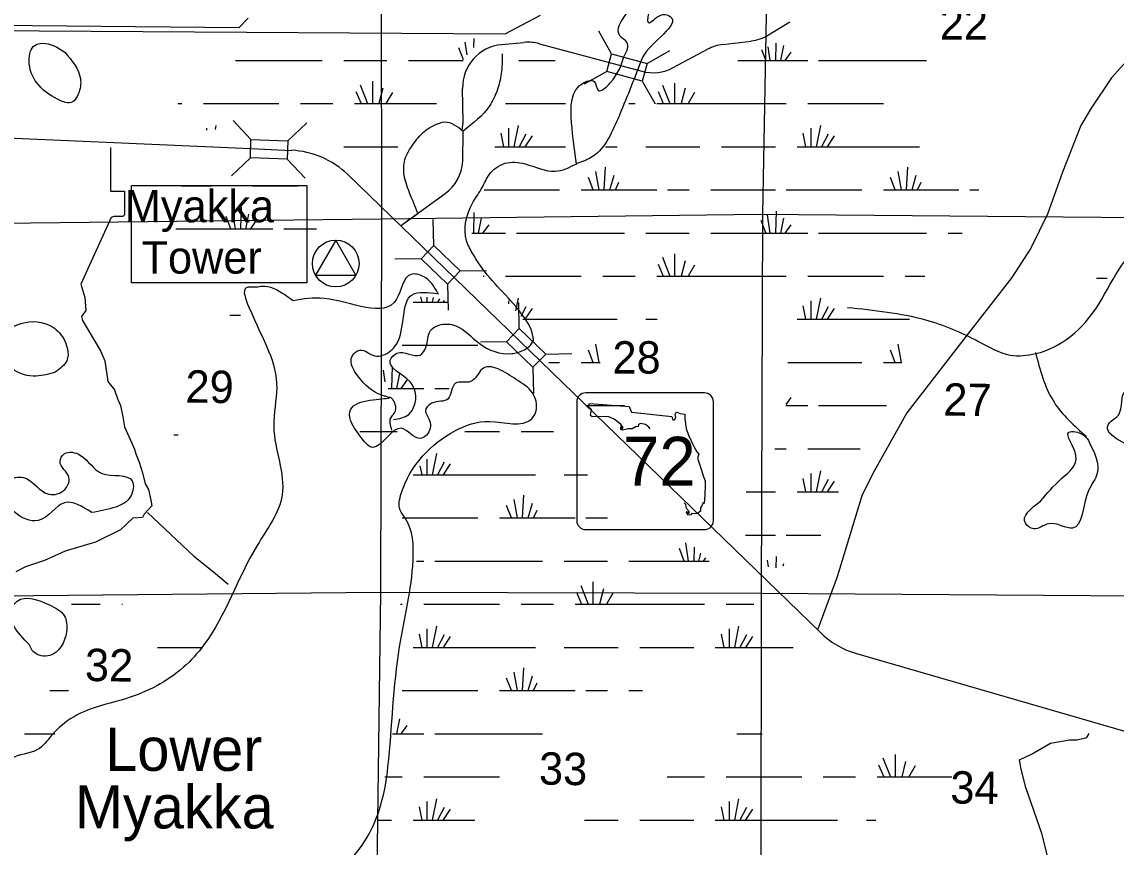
# Model space of a CAD drawing. Extents: x 408847 to 817539, y 923858 to 1151780.
# Drawn here: x 547942 to 563149, y 1047697 to 1059169 of the extents above; entities that cross this region are included whole.
import ezdxf

# ---------------------------------------------------------------- set-up
doc = ezdxf.new("R2010")
doc.units = 0
for name, color, linetype in [('Bridges', 7, 'Continuous'), ('Culture', 7, 'Continuous'), ('Lakes and Ponds', 7, 'Continuous'), ('Level 12', 7, 'Continuous'), ('Level 41', 7, 'Continuous'), ('Level 42', 7, 'Continuous'), ('Level 43', 7, 'Continuous'), ('Level 47', 7, 'Continuous'), ('Local Roads Paved', 7, 'Continuous'), ('Narrow River Creek and Branch and Slough', 7, 'Continuous'), ('Roadshields State Highways', 7, 'Continuous'), ('Section Lines', 7, 'Continuous'), ('State Park', 7, 'Continuous'), ('State Routes Highway Center Lines', 7, 'Continuous'), ('Swamps', 7, 'Continuous')]:
    doc.layers.add(name, color=color, linetype=linetype)

msp = doc.modelspace()

# ---------------------------------------------------------------- linework, layer by layer
at = {"layer": 'Bridges'}
for p, q in [((556137, 1058726), (555958, 1059041)), ((556631, 1058590), (556945, 1058769)), ((556069, 1058480), (555754, 1058301)), ((556562, 1058343), (556741, 1058028)), ((551125, 1057534), (550878, 1057798)), ((551637, 1057517), (551901, 1057765)), ((551117, 1057278), (550853, 1057030)), ((551629, 1057261), (551877, 1056997)), ((553667, 1056061), (553660, 1056423)), ((553489, 1055877), (553127, 1055871)), ((554035, 1055706), (554397, 1055712)), ((553857, 1055522), (553864, 1055160)), ((554854, 1054906), (554848, 1055268)), ((554676, 1054722), (554314, 1054716)), ((555223, 1054551), (555585, 1054557)), ((555045, 1054367), (555051, 1054005))]:
    msp.add_line(p, q, dxfattribs=at)
for points in [[(556137, 1058726), (556631, 1058590), (556562, 1058343), (556069, 1058480)], [(551125, 1057534), (551637, 1057517), (551629, 1057261), (551117, 1057278)], [(553667, 1056061), (554035, 1055706), (553857, 1055522), (553489, 1055877)], [(554854, 1054906), (555223, 1054551), (555045, 1054367), (554676, 1054722)]]:
    msp.add_lwpolyline(points, close=True, dxfattribs=at)
at = {"layer": 'Culture'}
msp.add_lwpolyline([(552023, 1055648), (552585, 1055648), (552304, 1056135)], close=True, dxfattribs=at)
msp.add_circle((552304, 1055810), 325, dxfattribs=at)
at = {"layer": 'Lakes and Ponds'}
for p, q in [((555641, 1057198), (555650, 1057193)), ((553732, 1055390), (553722, 1055400))]:
    msp.add_line(p, q, dxfattribs=at)
for points in [[(556309, 1058685), (556351, 1058886), (556255, 1058971), (556356, 1059297), (556451, 1059406), (556733, 1059847), (557074, 1059998), (557133, 1060207), (557234, 1060270), (557345, 1060172), (557257, 1059852), (557146, 1059776), (556787, 1059581), (556664, 1059155), (556850, 1059271), (556951, 1059245), (556570, 1058681), (556545, 1058620)], [(548540, 1058747), (548226, 1058872), (548121, 1058842), (548043, 1058632), (548437, 1058094), (548650, 1058059), (548726, 1058164), (548756, 1058378), (548540, 1058747)], [(555650, 1057193), (555582, 1057770), (555758, 1058328), (555896, 1058341), (555949, 1058220), (556116, 1058320), (556309, 1058685)], [(556545, 1058620), (556223, 1057818), (555846, 1057279), (555641, 1057198)], [(553722, 1055400), (553521, 1055631), (553348, 1055658), (553150, 1055314), (552146, 1055324), (551711, 1055293)], [(551711, 1055293), (551590, 1055377), (551281, 1055491), (551201, 1055481), (551060, 1055471), (551097, 1055204), (551483, 1054080), (551442, 1053545), (551559, 1052590), (551211, 1051890), (550468, 1050503), (550189, 1050197), (549395, 1049764), (548804, 1049579), (548462, 1049360), (548350, 1049243), (548161, 1049052), (547794, 1048927), (547627, 1048491), (547638, 1047921), (547608, 1047674), (546454, 1047613), (546109, 1047460), (545990, 1047112), (546360, 1046135), (546342, 1045807), (546223, 1045704), (545885, 1045633), (545598, 1044356), (545089, 1043682), (544808, 1042649), (544826, 1042544), (544941, 1042105), (544737, 1042014), (544903, 1041875), (545016, 1041929), (545126, 1042134), (545113, 1042460), (545172, 1043016), (545967, 1044163), (546271, 1044606), (546310, 1044928), (546115, 1045140), (546091, 1045363), (546521, 1045487), (546653, 1045452), (547247, 1045445), (547839, 1045684), (548058, 1045859), (548124, 1046099), (548220, 1046456), (548064, 1046678), (547763, 1046895), (547895, 1046973), (548594, 1046679), (549802, 1046381), (550350, 1046366), (551126, 1046460), (552019, 1047061), (552705, 1047775), (553018, 1048713), (553030, 1048817), (553191, 1050483), (553379, 1051686), (553269, 1052268), (553198, 1052383), (553214, 1052614), (553967, 1053487), (554441, 1053615), (555027, 1053653), (555088, 1053763), (555037, 1054014), (554817, 1054195), (554337, 1054341), (554178, 1054169), (553968, 1054145), (553866, 1053930), (553637, 1053867), (553551, 1053758), (553598, 1053653), (553584, 1053445), (553479, 1053378), (553217, 1053519), (552820, 1053254), (552629, 1053430), (552500, 1053747), (552582, 1053852), (553029, 1053954), (552980, 1053968), (552656, 1054190), (552535, 1054529), (552638, 1054606), (552849, 1054526), (552956, 1054536), (553148, 1054690), (553366, 1055376), (553732, 1055390)], [(548407, 1054299), (548565, 1054459), (548505, 1054791), (548312, 1054958), (547877, 1054957), (547686, 1054786), (547688, 1054665), (547819, 1054346), (548142, 1054245), (548407, 1054299)], [(563956, 1053465), (563984, 1053534), (563904, 1053662), (563554, 1053810), (563404, 1054017), (563292, 1054037), (563182, 1053703), (563079, 1053619), (563027, 1053513), (563113, 1053403), (563451, 1053266), (563956, 1053465)], [(562102, 1052511), (561889, 1052199), (562004, 1052123), (562211, 1052192), (562542, 1052129), (562767, 1052653), (562887, 1052895), (562778, 1053319), (562700, 1053424), (562492, 1053464), (562591, 1053139), (562389, 1052819), (562102, 1052511)], [(548913, 1052348), (549249, 1052425), (549453, 1052570), (549475, 1052787), (549054, 1052892), (548754, 1053145), (548532, 1053163), (548472, 1053058), (548597, 1052839), (548490, 1052630), (548263, 1052624), (547963, 1052837), (547755, 1052780), (547696, 1052675), (548169, 1052236), (548535, 1052485), (548913, 1052348)], [(548042, 1050514), (548107, 1050409), (548332, 1050361), (548562, 1050689), (548529, 1050918), (548324, 1051064), (547878, 1051117), (547795, 1051010), (548042, 1050514)]]:
    msp.add_spline(points, degree=3, dxfattribs=at)
at = {"layer": 'Level 12'}
for p, q in [((545296, 1059144), (550961, 1059091)), ((550961, 1059091), (551089, 1059219))]:
    msp.add_line(p, q, dxfattribs=at)
at = {"layer": 'Level 41'}
msp.add_lwpolyline([(549466, 1056894), (551901, 1056894), (551901, 1055540), (549466, 1055540)], close=True, dxfattribs=at)
at = {"layer": 'Local Roads Paved'}
for p, q in [((558317, 1058987), (558614, 1059169)), ((558317, 1058987), (558614, 1059169)), ((554608, 1058853), (554920, 1058883)), ((554608, 1058853), (554920, 1058883)), ((555134, 1058865), (556556, 1058483)), ((555134, 1058865), (556556, 1058483)), ((557682, 1058855), (558077, 1058903)), ((557682, 1058855), (558077, 1058903)), ((556994, 1058533), (557472, 1058788)), ((556994, 1058533), (557472, 1058788)), ((554075, 1057775), (554066, 1058244)), ((554075, 1057775), (554066, 1058244)), ((554060, 1057659), (554075, 1057775)), ((554070, 1057231), (554074, 1057652)), ((553205, 1056332), (553824, 1056782)), ((553205, 1056332), (553446, 1056507))]:
    msp.add_line(p, q, dxfattribs=at)
for points in [[(563504, 1058861), (563086, 1058389), (562801, 1057971), (562658, 1057729), (562405, 1057080), (562196, 1056497), (561965, 1056024), (561701, 1055617), (560998, 1054715), (560239, 1053736), (559767, 1052889), (559613, 1052581), (559272, 1051455), (559004, 1050727)], [(549173, 1057425), (549173, 1056817), (549368, 1056817), (549368, 1056817), (549368, 1056623), (549368, 1056485), (549345, 1056462), (549219, 1056462), (549185, 1056451), (548761, 1055522), (548818, 1055339), (548829, 1055156), (548772, 1055075), (548784, 1055018), (549036, 1054594), (549093, 1054457), (549139, 1054170), (549230, 1054056), (549276, 1053918), (549311, 1053838), (549345, 1053677), (549368, 1053540), (549471, 1053311), (549505, 1053230), (549528, 1053162), (549574, 1053047), (549620, 1052898), (549654, 1052749), (549700, 1052669), (549734, 1052520), (549746, 1052440), (549643, 1052325), (549620, 1052279), (549482, 1052268), (549311, 1052107), (548967, 1051935), (548543, 1051809), (548257, 1051683), (547993, 1051592), (547856, 1051523)], [(549689, 1052348), (550330, 1051741), (550605, 1051523), (550811, 1051351)], [(562444, 1045932), (562433, 1046447), (562301, 1047151), (562115, 1047888), (561895, 1048526), (561829, 1048779), (561807, 1048911), (561972, 1048988), (562235, 1049142), (562499, 1049186), (562609, 1049186), (562741, 1049219), (562774, 1049274)]]:
    msp.add_lwpolyline(points, dxfattribs=at)
for centre, start, end in [((558004, 1059499), 277.0197, 301.4719), ((558004, 1059499), 277.0197, 301.4719), ((554666, 1058255), 95.5848, 181.0944), ((554666, 1058255), 95.5848, 181.0944), ((554978, 1058286), 74.9456, 95.5849), ((554978, 1058286), 74.9456, 95.5849), ((557755, 1058259), 97.0196, 118.1097), ((557755, 1058259), 97.0196, 118.1097), ((556712, 1059062), 254.9456, 298.1098), ((556712, 1059062), 254.9456, 298.1098), ((553471, 1057267), 306.0117, 356.5362)]:
    msp.add_arc(centre, 600, start, end, dxfattribs=at)
for points in [[(554615, 1058724), (554604, 1058448), (554546, 1058217), (554444, 1058006), (554074, 1057652)], [(553446, 1056507), (553330, 1056793), (553255, 1057037), (553266, 1057253), (553382, 1057471), (553525, 1057637), (553669, 1057730), (553820, 1057778), (554074, 1057652)]]:
    msp.add_spline(points, degree=3, dxfattribs=at)
at = {"layer": 'Narrow River Creek and Branch and Slough'}
msp.add_lwpolyline([(554834, 1054573), (554927, 1054611), (554991, 1054654), (555011, 1054674), (555040, 1054718), (555052, 1054741)], dxfattribs=at)
for points in [[(555052, 1054741), (555043, 1054802), (554873, 1055131), (554319, 1055772), (554214, 1055938), (554123, 1056124), (554214, 1056666), (554339, 1056867), (554435, 1057043), (554656, 1057203), (554934, 1057195), (555355, 1057092), (555645, 1057193)], [(559417, 1055199), (560500, 1055027), (561234, 1054728), (561677, 1054538), (562030, 1054557), (562908, 1055247), (563657, 1056051), (564199, 1056046), (564363, 1056264), (564803, 1056101), (565241, 1056102), (565613, 1055580), (565587, 1055366), (565483, 1055119), (565670, 1054911), (566108, 1054655), (566363, 1054220)], [(553105, 1053643), (553318, 1053712), (553396, 1053833), (553336, 1054165), (553062, 1054464), (553154, 1054565), (553476, 1054538), (553558, 1054643), (553620, 1054877), (553737, 1054953), (553973, 1054943), (554295, 1054703), (554751, 1054557), (554834, 1054573)], [(562028, 1054575), (562281, 1053890), (562737, 1053405)], [(553046, 1053955), (553080, 1053936), (553109, 1053896), (553134, 1053801), (553123, 1053745), (553090, 1053697), (553057, 1053642), (553060, 1053576), (553069, 1053533), (553085, 1053495)]]:
    msp.add_spline(points, degree=3, dxfattribs=at)
at = {"layer": 'Roadshields State Highways'}
for p, q in [((557428, 1054011), (555778, 1054011)), ((555653, 1053886), (555653, 1052236)), ((557553, 1052236), (557553, 1053886)), ((555778, 1052111), (557428, 1052111))]:
    msp.add_line(p, q, dxfattribs=at)
for points in [[(556672, 1053512), (556653, 1053537), (556610, 1053574), (556541, 1053584), (556511, 1053570), (556508, 1053541), (556478, 1053544), (556425, 1053514), (556366, 1053514), (556290, 1053495), (556264, 1053501), (556267, 1053544), (556284, 1053514), (556300, 1053531), (556264, 1053574), (556208, 1053617), (556171, 1053646), (556099, 1053679), (556023, 1053683), (555868, 1053679), (555845, 1053696), (555858, 1053782), (555812, 1053824), (555829, 1053864)], [(555829, 1053864), (556382, 1053824), (556412, 1053745), (556976, 1053683), (556989, 1053636), (557012, 1053636), (557029, 1053669), (557019, 1053709), (557038, 1053749), (557088, 1053725), (557154, 1053716), (557154, 1053653), (557174, 1053518), (557207, 1053422), (557276, 1053274), (557322, 1053194), (557348, 1053158), (557329, 1053102), (557355, 1053033), (557388, 1052937), (557411, 1052858), (557437, 1052789), (557437, 1052726), (557431, 1052601), (557427, 1052528), (557424, 1052472), (557411, 1052489), (557394, 1052452), (557371, 1052413), (557371, 1052367), (557332, 1052337), (557289, 1052330), (557253, 1052337), (557240, 1052317), (557197, 1052310), (557177, 1052347), (557187, 1052363), (557200, 1052340), (557216, 1052334), (557216, 1052363), (557180, 1052406), (557167, 1052459), (557145, 1052483)]]:
    msp.add_lwpolyline(points, dxfattribs=at)
for centre, start, end in [((555778, 1053886), 90, 180), ((557428, 1053886), 0, 90), ((555778, 1052236), 180, 270), ((557428, 1052236), 270, 0)]:
    msp.add_arc(centre, 125, start, end, dxfattribs=at)
at = {"layer": 'Section Lines'}
for p, q in [((552930, 1061674), (552941, 1056432)), ((558334, 1061654), (558233, 1056494)), ((547660, 1056371), (552941, 1056432)), ((552941, 1056432), (552927, 1051241)), ((552941, 1056432), (558213, 1056494)), ((558213, 1056494), (563464, 1056450)), ((558233, 1056494), (558217, 1051227)), ((547615, 1051190), (552927, 1051241)), ((552927, 1051241), (552856, 1046025)), ((552927, 1051241), (558217, 1051227)), ((558218, 1051275), (558207, 1045966)), ((558217, 1051227), (563447, 1051191))]:
    msp.add_line(p, q, dxfattribs=at)
at = {"layer": 'State Park'}
msp.add_lwpolyline([(543571, 1043078), (543581, 1043265), (542259, 1043316), (542432, 1046159), (542425, 1059084), (554660, 1059003), (555149, 1059262)], dxfattribs=at)
at = {"layer": 'State Routes Highway Center Lines'}
for p, q in [((551123, 1057408), (551688, 1057383)), ((552471, 1057046), (559039, 1050679)), ((559540, 1050388), (569161, 1047598))]:
    msp.add_line(p, q, dxfattribs=at)
msp.add_lwpolyline([(539784, 1058895), (539798, 1058892), (539799, 1058892), (545306, 1057682), (545327, 1057677), (545347, 1057673), (545368, 1057670), (545389, 1057667), (545410, 1057664), (545430, 1057661), (545451, 1057659), (545472, 1057657), (545493, 1057656), (545511, 1057655), (551123, 1057408)], dxfattribs=at)
for centre, start, end in [((551635, 1056185), 45.8894, 87.4828), ((559874, 1051540), 225.8893, 253.8269)]:
    msp.add_arc(centre, 1200, start, end, dxfattribs=at)
at = {"layer": 'Swamps'}
for p, q in [((558488, 1058633), (558531, 1058839)), ((558550, 1058633), (558634, 1058747)), ((552415, 1058634), (553015, 1058634)), ((553315, 1058634), (553915, 1058634)), ((558115, 1058634), (558865, 1058634)), ((559015, 1058634), (560515, 1058634)), ((552644, 1058296), (552747, 1058034)), ((552813, 1058345), (552813, 1058034)), ((552958, 1058248), (552905, 1058033)), ((557158, 1058248), (557105, 1058033)), ((552584, 1058200), (552655, 1058034)), ((553091, 1058187), (553002, 1058034)), ((556784, 1058200), (556855, 1058034)), ((557291, 1058187), (557202, 1058034)), ((550465, 1058034), (551515, 1058034)), ((551815, 1058034), (552265, 1058034)), ((554665, 1058034), (555498, 1058034)), ((556375, 1058034), (556465, 1058034)), ((556765, 1058034), (558115, 1058034)), ((558115, 1058034), (558565, 1058034)), ((558865, 1058034), (559915, 1058034)), ((554597, 1057620), (554634, 1057434)), ((554706, 1057692), (554706, 1057434)), ((554839, 1057728), (554780, 1057434)), ((554947, 1057608), (554853, 1057433)), ((558797, 1057620), (558834, 1057434)), ((558906, 1057692), (558906, 1057434)), ((559039, 1057728), (558980, 1057434)), ((559147, 1057608), (559053, 1057433)), ((555032, 1057583), (554933, 1057434)), ((559232, 1057583), (559133, 1057434)), ((552415, 1057434), (553165, 1057434)), ((554515, 1057434), (555498, 1057434)), ((556054, 1057434), (556215, 1057434)), ((556615, 1057434), (557365, 1057434)), ((557665, 1057434), (558115, 1057434)), ((558115, 1057434), (558415, 1057434)), ((558715, 1057434), (560415, 1057434)), ((556036, 1056834), (556054, 1057150)), ((560236, 1056834), (560254, 1057150)), ((555880, 1056834), (555815, 1057006)), ((555965, 1056834), (555919, 1057088)), ((556113, 1056834), (556171, 1057038)), ((560080, 1056834), (560015, 1057006)), ((560165, 1056834), (560119, 1057088)), ((560313, 1056834), (560371, 1057038)), ((556190, 1056834), (556238, 1056942)), ((560390, 1056834), (560438, 1056942)), ((554365, 1056834), (555415, 1056834)), ((555715, 1056834), (556765, 1056834)), ((556915, 1056834), (557215, 1056834)), ((557515, 1056834), (558115, 1056834)), ((558115, 1056834), (558415, 1056834)), ((558565, 1056834), (559615, 1056834)), ((559915, 1056834), (560965, 1056834)), ((550909, 1056290), (550870, 1056543)), ((550987, 1056290), (550993, 1056593)), ((550847, 1056291), (550781, 1056463)), ((551054, 1056289), (551097, 1056495)), ((551117, 1056289), (551200, 1056403)), ((554288, 1056233), (554331, 1056439)), ((558280, 1056235), (558214, 1056407)), ((558343, 1056234), (558303, 1056487)), ((558421, 1056234), (558427, 1056537)), ((558488, 1056233), (558531, 1056439)), ((550081, 1056290), (550681, 1056290)), ((550681, 1056290), (551431, 1056290)), ((554350, 1056233), (554434, 1056347)), ((558550, 1056233), (558634, 1056347)), ((554815, 1056234), (556315, 1056234)), ((556615, 1056234), (557215, 1056234)), ((557515, 1056234), (558115, 1056234)), ((558115, 1056234), (558865, 1056234)), ((559015, 1056234), (560515, 1056234)), ((557013, 1055945), (557013, 1055634)), ((556784, 1055800), (556855, 1055634)), ((556844, 1055896), (556947, 1055634)), ((557158, 1055848), (557105, 1055633)), ((557291, 1055787), (557202, 1055634)), ((554665, 1055634), (555715, 1055634)), ((556015, 1055634), (556465, 1055634)), ((556765, 1055634), (558115, 1055634)), ((558115, 1055634), (558565, 1055634)), ((558865, 1055634), (559915, 1055634)), ((559039, 1055328), (558980, 1055034)), ((555032, 1055183), (554933, 1055034)), ((558797, 1055220), (558834, 1055034)), ((558906, 1055292), (558906, 1055034)), ((559147, 1055208), (559053, 1055033)), ((559232, 1055183), (559133, 1055034)), ((553229, 1054673), (554279, 1054673)), ((555880, 1054434), (555815, 1054606)), ((555965, 1054434), (555919, 1054688)), ((560080, 1054434), (560015, 1054606)), ((560165, 1054434), (560119, 1054688)), ((553085, 1054073), (553091, 1054377)), ((553152, 1054073), (553195, 1054279)), ((553215, 1054073), (553298, 1054186)), ((554879, 1053473), (555329, 1053473)), ((553812, 1053047), (553718, 1052872)), ((553896, 1053023), (553797, 1052874)), ((558906, 1052892), (558906, 1052634)), ((559039, 1052928), (558980, 1052634)), ((553379, 1052873), (555079, 1052873)), ((558797, 1052820), (558834, 1052634)), ((559147, 1052808), (559053, 1052633)), ((559232, 1052783), (559133, 1052634)), ((554901, 1052273), (554918, 1052589)), ((558115, 1052634), (558415, 1052634)), ((554745, 1052273), (554679, 1052445)), ((554830, 1052273), (554783, 1052528)), ((554977, 1052273), (555036, 1052477)), ((555054, 1052273), (555103, 1052382)), ((553229, 1052273), (554279, 1052273)), ((554579, 1052273), (555629, 1052273)), ((555779, 1052273), (556079, 1052273)), ((558115, 1052034), (558415, 1052034)), ((557145, 1051674), (557079, 1051847)), ((557207, 1051673), (557168, 1051926)), ((553679, 1051673), (555179, 1051673)), ((555479, 1051673), (556079, 1051673)), ((556379, 1051673), (556979, 1051673)), ((555878, 1051384), (555878, 1051073)), ((555648, 1051239), (555719, 1051073)), ((555709, 1051336), (555812, 1051073)), ((556023, 1051287), (555969, 1051073)), ((556156, 1051227), (556066, 1051073)), ((553529, 1051073), (554579, 1051073)), ((554879, 1051073), (555329, 1051073)), ((555629, 1051073), (556979, 1051073)), ((556979, 1051073), (557429, 1051073)), ((553703, 1050768), (553644, 1050473)), ((557903, 1050768), (557844, 1050473)), ((553461, 1050659), (553499, 1050473)), ((553570, 1050732), (553570, 1050473)), ((553812, 1050647), (553718, 1050472)), ((553896, 1050623), (553797, 1050474)), ((557661, 1050659), (557699, 1050473)), ((557770, 1050732), (557770, 1050473)), ((558012, 1050647), (557918, 1050472)), ((558096, 1050623), (557997, 1050474)), ((553379, 1050473), (555079, 1050473)), ((555479, 1050473), (556229, 1050473)), ((556529, 1050473), (556979, 1050473)), ((556979, 1050473), (557279, 1050473)), ((554901, 1049873), (554918, 1050189)), ((554745, 1049873), (554679, 1050045)), ((554830, 1049873), (554783, 1050128)), ((554977, 1049873), (555036, 1050077)), ((548579, 1049873), (548589, 1049873)), ((553229, 1049873), (554279, 1049873)), ((554579, 1049873), (555629, 1049873)), ((555054, 1049873), (555103, 1049982)), ((555779, 1049873), (556079, 1049873)), ((553152, 1049273), (553195, 1049479)), ((553215, 1049273), (553298, 1049386)), ((553679, 1049273), (555179, 1049273)), ((560078, 1048984), (560078, 1048673)), ((559848, 1048839), (559919, 1048673)), ((559909, 1048936), (560012, 1048673)), ((560223, 1048887), (560169, 1048673)), ((560356, 1048827), (560266, 1048673)), ((553529, 1048673), (554579, 1048673)), ((556979, 1048673), (557429, 1048673)), ((557729, 1048673), (558779, 1048673)), ((559079, 1048673), (559529, 1048673)), ((559829, 1048673), (560865, 1048673)), ((553570, 1048332), (553570, 1048073)), ((553703, 1048368), (553644, 1048073)), ((557770, 1048332), (557770, 1048073)), ((557903, 1048368), (557844, 1048073)), ((553461, 1048259), (553499, 1048073)), ((553812, 1048247), (553718, 1048072)), ((553896, 1048223), (553797, 1048074)), ((557661, 1048259), (557699, 1048073)), ((558012, 1048247), (557918, 1048072)), ((558096, 1048223), (557997, 1048074)), ((552887, 1048073), (553079, 1048073)), ((556529, 1048073), (556979, 1048073)), ((556979, 1048073), (557279, 1048073)), ((557579, 1048073), (559279, 1048073))]:
    msp.add_line(p, q, dxfattribs=at)
for points in [[(554131, 1058710), (554103, 1058887)], [(554224, 1058812), (554227, 1058937)], [(558343, 1058634), (558313, 1058822)], [(558421, 1058634), (558425, 1058874)], [(554078, 1058640), (554014, 1058807)], [(558280, 1058635), (558225, 1058780)], [(550913, 1058634), (552115, 1058634)], [(553915, 1058634), (554073, 1058634)], [(554847, 1058634), (555351, 1058634)], [(557891, 1058634), (558115, 1058634)], [(556846, 1058291), (556947, 1058034)], [(557013, 1058317), (557013, 1058034)], [(550111, 1058034), (550165, 1058034)], [(552565, 1058034), (553705, 1058034)], [(550506, 1057692), (550506, 1057666)], [(550639, 1057728), (550628, 1057675)], [(550156, 1056890), (550584, 1056890)], [(551147, 1056890), (551775, 1056890)], [(561115, 1056834), (561242, 1056834)], [(554221, 1056234), (554226, 1056517)], [(549779, 1056290), (549781, 1056290)], [(551581, 1056290), (552036, 1056290)], [(554195, 1056234), (554665, 1056234)], [(560815, 1056234), (561008, 1056234)], [(554352, 1055634), (554365, 1055634)], [(560215, 1055634), (560489, 1055634)], [(562875, 1055606), (563025, 1055606)], [(553484, 1055345), (553499, 1055273)], [(553570, 1055343), (553570, 1055273)], [(553657, 1055336), (553644, 1055273)], [(554839, 1055328), (554804, 1055154)], [(553379, 1055273), (553856, 1055273)], [(553744, 1055321), (553718, 1055272)], [(553812, 1055297), (553797, 1055274)], [(554706, 1055292), (554706, 1055251)], [(554947, 1055208), (554875, 1055074)], [(550833, 1055090), (550981, 1055090)], [(554905, 1055034), (556215, 1055034)], [(556615, 1055034), (556773, 1055034)], [(558715, 1055034), (560276, 1055034)], [(555264, 1054434), (555415, 1054434)], [(555715, 1054434), (555977, 1054434)], [(558586, 1054434), (559615, 1054434)], [(559915, 1054434), (560171, 1054434)], [(552993, 1054164), (552968, 1054326)], [(553031, 1054073), (553529, 1054073)], [(553679, 1054073), (553882, 1054073)], [(555780, 1053834), (556315, 1053834)], [(558561, 1053834), (558865, 1053834)], [(558563, 1053850), (558634, 1053947)], [(559015, 1053834), (559959, 1053834)], [(550056, 1053429), (550116, 1053429)], [(552637, 1053473), (552779, 1053473)], [(552779, 1053473), (553159, 1053473)], [(554099, 1053473), (554579, 1053473)], [(558408, 1053234), (558565, 1053234)], [(558865, 1053234), (559591, 1053234)], [(553570, 1053088), (553570, 1052873)], [(553703, 1053168), (553644, 1052873)], [(553474, 1052996), (553499, 1052873)], [(555479, 1052873), (555804, 1052873)], [(558007, 1052634), (558115, 1052634)], [(558715, 1052634), (559291, 1052634)], [(557997, 1052034), (558115, 1052034)], [(558565, 1052034), (559046, 1052034)], [(557285, 1051673), (557289, 1051865)], [(557352, 1051673), (557376, 1051784)], [(557415, 1051673), (557447, 1051717)], [(558318, 1051591), (558303, 1051687)], [(558424, 1051578), (558427, 1051737)], [(553428, 1051673), (553529, 1051673)], [(556979, 1051673), (557495, 1051673)], [(558524, 1051605), (558531, 1051639)], [(548630, 1051073), (549029, 1051073)], [(549329, 1051073), (549340, 1051073)], [(553204, 1051073), (553229, 1051073)], [(557729, 1051073), (558113, 1051073)], [(549828, 1050473), (550432, 1050473)], [(557579, 1050473), (558662, 1050473)], [(548329, 1049873), (548579, 1049873)], [(556379, 1049873), (556566, 1049873)], [(547979, 1049273), (548400, 1049273)], [(553093, 1049273), (553529, 1049273)], [(557879, 1049273), (558232, 1049273)], [(552984, 1048673), (553229, 1048673)], [(556910, 1048673), (556979, 1048673)], [(553379, 1048073), (554239, 1048073)], [(555760, 1048073), (556229, 1048073)], [(559679, 1048073), (559809, 1048073)]]:
    msp.add_lwpolyline(points, dxfattribs=at)

# ---------------------------------------------------------------- texts
at = {"layer": 'Level 42'}
for s, p in [('Lower', (549100, 1048757)), ('Myakka', (548678, 1047957))]:
    msp.add_text(s, height=600, rotation=360, dxfattribs=at).set_placement(p)
at = {"layer": 'Level 43'}
for s, rotation, p in [('22', 359.9999, (560698, 1058922)), ('28', 360, (556150, 1054280)), ('29', 359.0617, (550213, 1053878)), ('27', 359.0617, (560744, 1053697)), ('32', 359.0617, (548816, 1050007)), ('33', 359.0617, (555126, 1048567)), ('34', 359.0617, (560843, 1048304))]:
    msp.add_text(s, height=450, rotation=rotation, dxfattribs=at).set_placement(p)
at = {"layer": 'Level 47'}
for s, p in [('Myakka', (549373, 1056383)), ('Tower', (549605, 1055670))]:
    msp.add_text(s, height=450, rotation=360, dxfattribs=at).set_placement(p)
at = {"layer": 'Roadshields State Highways'}
msp.add_text('72', height=680, dxfattribs=at).set_placement((556296, 1052721))

doc.saveas('drawing.dxf')
